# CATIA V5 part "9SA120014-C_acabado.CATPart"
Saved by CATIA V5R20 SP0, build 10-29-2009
Part number: 9SA120014-C_acabado
Revision: ANY
Definition: UNKNOWN
Nomenclature: 9SA120014-C_acabado
Source: Unknown
Bounding box of the stored display mesh (mm): x -5.85 to 5.85, y 0 to 14, z -6 to 6
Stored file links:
  C:\Users\Utente\Desktop\IO LAVORO\3D X SITO CF\CUMSA\3D files SA\SA 120014\9SA120014-C_acabado.CATPart
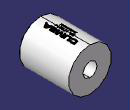
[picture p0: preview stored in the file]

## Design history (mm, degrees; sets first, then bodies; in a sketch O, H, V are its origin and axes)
Body1 "Envolver1" (main body)
  Solid1: solid without history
